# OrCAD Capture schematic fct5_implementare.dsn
size A
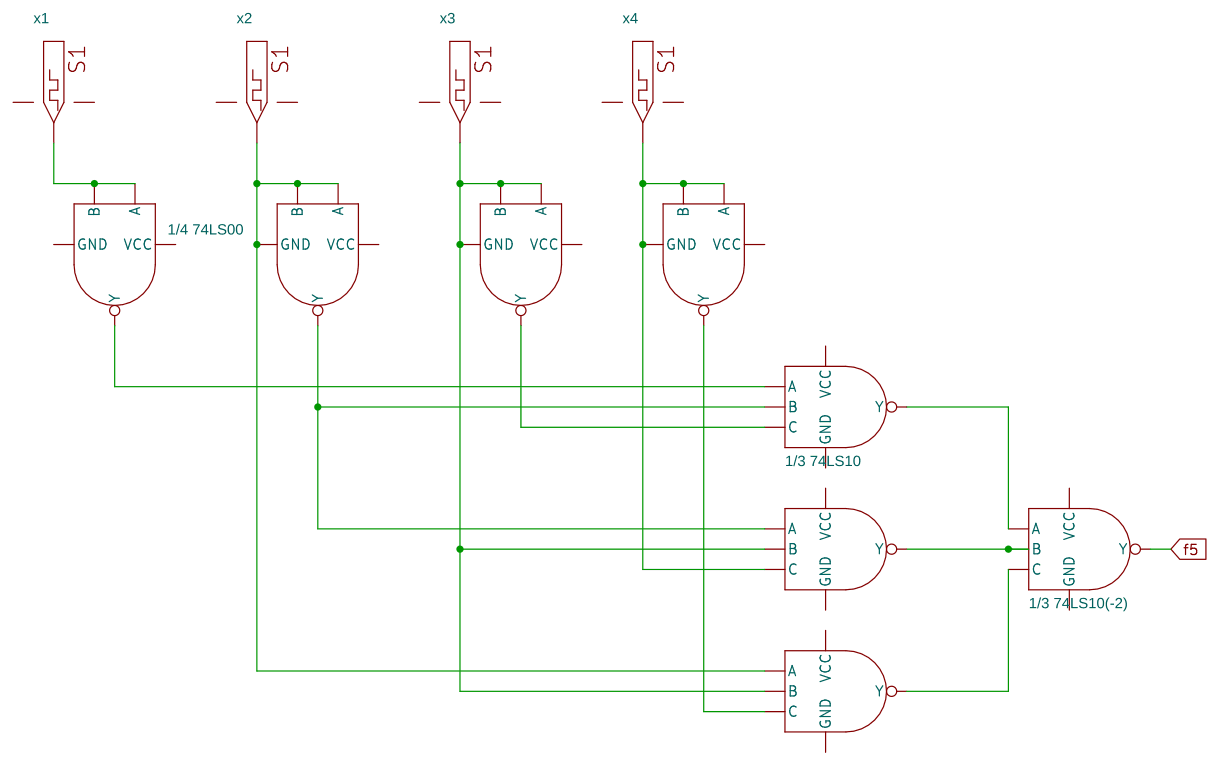
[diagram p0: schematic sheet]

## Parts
U3  1/4 74LS00  [DIP.100/14/W.300/L.800]  (section B)
U4  1/3 74LS10  [DIP.100/14/W.300/L.800]  (section A)
U5  1/4 74LS00  [DIP.100/14/W.300/L.800]  (section B)
U6  1/4 74LS00  [DIP.100/14/W.300/L.800]  (section B)
U7  1/4 74LS00  [DIP.100/14/W.300/L.800]  (section B)
U8  1/3 74LS10  [DIP.100/14/W.300/L.800]  (sections A,B,C)
x1  DigStim1
x2  DigStim1
x3  DigStim1
x4  DigStim1

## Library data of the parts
U3 U5-U7 = 74LS00
U4 U8 = 74LS10
x1-x4 = DigStim1

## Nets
GND: U3.7(GND) U4.7(GND) U5.7(GND) U6.7(GND) U7.7(GND) U8.7(GND) x1.3(GND) x2.3(GND) x3.3(GND) x4.3(GND)
VCC: U3.14(VCC) U4.14(VCC) U5.14(VCC) U6.14(VCC) U7.14(VCC) U8.14(VCC) x1.2(VCC) x2.2(VCC) x3.2(VCC) x4.2(VCC)
f5: U8.8(Y)
N15883: U3.4(A) U3.5(B) x1.OUT
N15901: U5.4(A) U5.5(B) U8.3(A) x2.OUT
N15905: U6.4(A) U6.5(B) U8.2(B) U8.4(B) x3.OUT
N15927: U7.4(A) U7.5(B) U8.13(C) x4.OUT
N16193: U3.6(Y) U4.1(A)
N16200: U4.2(B) U5.6(Y) U8.1(A)
N16207: U4.13(C) U6.6(Y)
N16255: U8.6(Y) U8.11(C)
N16262: U8.10(B) U8.12(Y)
N16271: U4.12(Y) U8.9(A)
N16284: U7.6(Y) U8.5(C)
